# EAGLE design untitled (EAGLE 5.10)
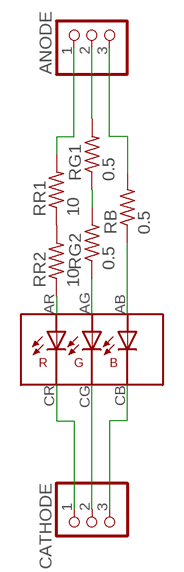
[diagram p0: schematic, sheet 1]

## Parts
ANODE  PINHD-1X3  [1X03]
CATHODE  PINHD-1X3  [1X03]
RB  0.5  R-US_M1206  [M1206]
RG1  0.5  R-US_M1206  [M1206]
RG2  0.5  R-US_M1206  [M1206]
RR1  10  R-US_R1210  [R1210]
RR2  10  R-US_R1210  [R1210]
U$1  LED-RGB-SMD-HB  [LED-RGB-SMD-HB]

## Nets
N$1: RR1.1 RR2.2
N$2: RG2.1 U$1.AG
N$3: RB.1 U$1.AB
N$4: CATHODE.2 U$1.CG
N$5: CATHODE.3 U$1.CB
N$6: CATHODE.1 U$1.CR
N$7: ANODE.3 RB.2
N$8: ANODE.1 RR1.2
N$9: RG1.1 RG2.2
N$10: ANODE.2 RG1.2
N$11: RR2.1 U$1.AR

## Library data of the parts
ANODE CATHODE = pinhead:PINHD-1X3: PIN HEADER
RB RG1 RG2 RR1 RR2 = resistor:R-US_: RESISTOR, American symbol
U$1 = trl:LED-RGB-SMD-HB

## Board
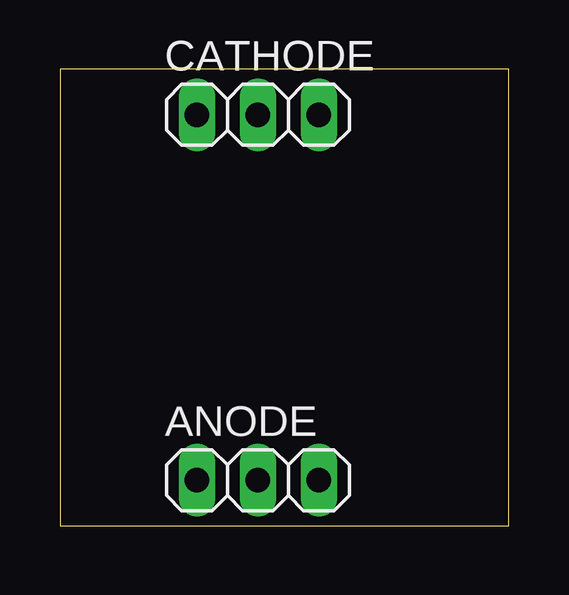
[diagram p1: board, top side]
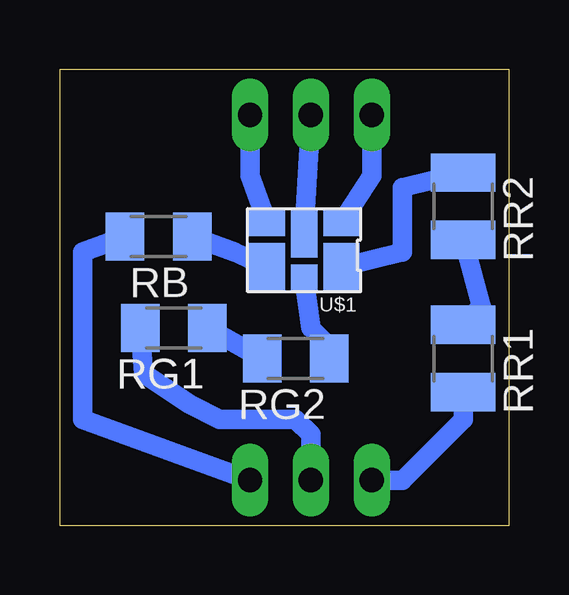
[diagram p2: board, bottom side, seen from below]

Size 18.72 x 19.04 mm. Coordinates in mm from the lower left corner, seen from the top.
Outline: 0,0 18.72,0 18.72,19.04 0,19.04 0,0
Copper layers (1*16): Top 0.035mm / dielectric 1.5mm / Bottom 0.035mm
Design rules "default": minimum track width 10mil, minimum drill 24mil, track to track 8mil, track to pad 8mil, pad to pad 8mil, via to via 8mil, smd to smd 8mil, copper to edge 40mil, drill to drill 8mil, minimum pad ring 10mil, minimum via ring 8mil, stop-mask expansion 4mil, vias tented up to drill 0mil, thermal gap 10mil

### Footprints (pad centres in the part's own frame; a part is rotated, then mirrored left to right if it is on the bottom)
1X03 = drill 1.016 long: 1 -2.54,0; 2 0,0; 3 2.54,0
M1206 = smd 1.6 x 2: 1 -1.4,0; 2 1.4,0
R1210 = smd 1.6 x 2.7: 1 -1.4,0; 2 1.4,0
LED-RGB-SMD-HB = smd 1.5 x 2: AB 3.1,0; AR 0,0 | smd 1.1 x 1.1: AG 1.55,0.45 | smd 1.5 x 1.1: CB 3.1,-1.85; CR 0,-1.85 | smd 1.1 x 2: CG 1.55,-1.4

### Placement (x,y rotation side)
ANODE  8.26,1.91 0 top
CATHODE  8.26,17.14 0 top
RB  14.61,12.06 180 bottom
RG1  13.97,8.26 180 bottom
RG2  8.89,6.99 180 bottom
RR1  1.91,6.99 270 bottom
RR2  1.91,13.34 270 bottom
U$1  6.99,10.79 180 bottom

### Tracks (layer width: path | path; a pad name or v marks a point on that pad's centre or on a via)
N$1
  Bottom 0.813: RR2.2 1.14,9.15 RR1.1
N$2
  Bottom 0.813: RG2.1 7.49,7.49 7.62,7.62 8.26,8.26 U$1.AG
N$3
  Bottom 0.813: U$1.AB 11.43,11.43 RB.1
N$4
  Bottom 0.813: U$1.CG CATHODE.2
N$5
  Bottom 0.813: U$1.CB 10.79,14.61 CATHODE.3
N$6
  Bottom 0.813: U$1.CR 5.71,14.61 CATHODE.1
N$7
  Bottom 0.813: ANODE.3 17.78,4.45 17.78,11.43 RB.2
N$8
  Bottom 0.813: RR1.2 1.91,4.45 4.45,1.91 ANODE.1
N$9
  Bottom 0.813: RG2.2 RG1.1
N$10
  Bottom 0.813: RG1.2 15.24,6.35 13.34,5.08 12.06,4.45 8.89,4.45 8.26,3.81 ANODE.2
N$11
  Bottom 0.813: U$1.AR 4.45,11.43 4.45,14.1 RR2.1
